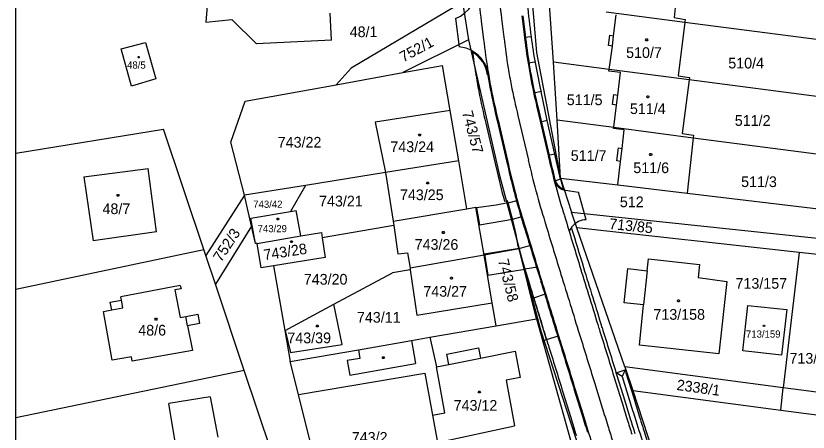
# Model space of a CAD drawing. Extents: x -639590 to -639298, y -1193269 to -1192863.
# Drawn here: x -639590.4 to -639464.3, y -1193049.8 to -1192983.6 of the extents above; entities that cross this region are included whole.
import ezdxf

# ---------------------------------------------------------------- set-up
doc = ezdxf.new("R2010")
doc.units = 0
for name, color, linetype in [('Vrstva 1', 7, 'Continuous'), ('Vrstva 19', 7, 'Continuous'), ('Vrstva 2', 7, 'Continuous'), ('Vrstva 20', 7, 'Continuous'), ('Vrstva 21', 7, 'Continuous'), ('Vrstva 4', 7, 'Continuous'), ('Vrstva 5', 7, 'Continuous'), ('Vrstva 61', 7, 'Continuous')]:
    doc.layers.add(name, color=color, linetype=linetype)

msp = doc.modelspace()

# ---------------------------------------------------------------- linework, layer by layer
at = {"layer": 'Vrstva 1'}
for p, q in [((-639558.69, -1192965.64), (-639560.13, -1192984.63)), ((-639509.02, -1192971.25), (-639507.5, -1192989.45)), ((-639484.75, -1192975.37), (-639485.61, -1192983.86)), ((-639519.26, -1192981.41), (-639537.01, -1192991.95)), ((-639519.26, -1192981.41), (-639518.33, -1192987.4)), ((-639504.82, -1192990.96), (-639505.43, -1192981.79)), ((-639540.12, -1192987.45), (-639540.36, -1192983.16)), ((-639496.42, -1192982.96), (-639483.9, -1192984.59)), ((-639485.61, -1192983.86), (-639483.85, -1192984.2)), ((-639560.13, -1192984.63), (-639555.99, -1192984.2)), ((-639555.99, -1192984.2), (-639552.08, -1192988.04)), ((-639483.9, -1192984.59), (-639484.96, -1192993.13)), ((-639483.85, -1192984.2), (-639483.9, -1192984.59)), ((-639483.9, -1192984.59), (-639461.13, -1192987.55)), ((-639540.12, -1192987.45), (-639552.08, -1192988.04)), ((-639518.33, -1192987.4), (-639528.76, -1192992.62)), ((-639518.33, -1192987.4), (-639513.38, -1193008.98)), ((-639573.61, -1192988.84), (-639569.73, -1192987.84)), ((-639571.96, -1192994.78), (-639573.61, -1192988.84)), ((-639569.73, -1192987.84), (-639568.13, -1192993.61)), ((-639507.5, -1192989.45), (-639503.7, -1193009.43)), ((-639504.21, -1193000.14), (-639504.82, -1192990.96)), ((-639495.93, -1192992.12), (-639504.82, -1192990.96)), ((-639537.01, -1192991.95), (-639539.42, -1192994.56)), ((-639539.42, -1192994.56), (-639528.76, -1192992.62)), ((-639528.76, -1192992.62), (-639522.49, -1192991.48)), ((-639521.26, -1192998.64), (-639522.49, -1192991.48)), ((-639495.97, -1192992.38), (-639495.93, -1192992.12)), ((-639494.14, -1192992.64), (-639495.97, -1192992.38)), ((-639483.21, -1192993.78), (-639495.93, -1192992.12)), ((-639494.57, -1192996.2), (-639494.14, -1192992.64)), ((-639568.13, -1192993.61), (-639571.96, -1192994.78)), ((-639484.96, -1192993.13), (-639483.16, -1192993.4)), ((-639483.21, -1192993.78), (-639484.31, -1193002.34)), ((-639483.16, -1192993.4), (-639483.21, -1192993.78)), ((-639460.55, -1192996.75), (-639483.21, -1192993.78)), ((-639553.86, -1192997.18), (-639539.42, -1192994.56)), ((-639495.4, -1192997.71), (-639495.21, -1192996.13)), ((-639495.21, -1192996.13), (-639494.57, -1192996.2)), ((-639556.15, -1193003.67), (-639553.86, -1192997.18)), ((-639494.77, -1192997.79), (-639495.4, -1192997.71)), ((-639521.26, -1192998.64), (-639533.19, -1193000.49)), ((-639519.89, -1193006.67), (-639521.26, -1192998.64)), ((-639495.21, -1193001.32), (-639494.77, -1192997.79)), ((-639503.7, -1193009.43), (-639504.21, -1193000.14)), ((-639504.21, -1193000.14), (-639495.21, -1193001.32)), ((-639533.19, -1193000.49), (-639531.56, -1193008.54)), ((-639495.23, -1193001.51), (-639495.21, -1193001.32)), ((-639493.52, -1193001.76), (-639495.23, -1193001.51)), ((-639495.21, -1193001.32), (-639482.56, -1193002.99)), ((-639590.39, -1193005.46), (-639566.86, -1193001.65)), ((-639560.45, -1193020.79), (-639566.86, -1193001.65)), ((-639493.88, -1193004.68), (-639493.52, -1193001.76)), ((-639484.31, -1193002.34), (-639482.51, -1193002.57)), ((-639482.51, -1193002.57), (-639482.56, -1193002.99)), ((-639553.99, -1193012.12), (-639556.15, -1193003.67)), ((-639482.56, -1193002.99), (-639483.54, -1193011.82)), ((-639482.56, -1193002.99), (-639459.99, -1193005.96)), ((-639494.73, -1193006.69), (-639494.47, -1193004.61)), ((-639494.47, -1193004.61), (-639493.88, -1193004.68)), ((-639519.89, -1193006.67), (-639531.56, -1193008.54)), ((-639518.6, -1193014.29), (-639519.89, -1193006.67)), ((-639494.13, -1193006.76), (-639494.73, -1193006.69)), ((-639494.58, -1193010.51), (-639494.13, -1193006.76)), ((-639579.55, -1193009.22), (-639569.3, -1193007.9)), ((-639568, -1193017.94), (-639569.3, -1193007.9)), ((-639531.56, -1193008.54), (-639544.27, -1193010.57)), ((-639531.56, -1193008.54), (-639530.31, -1193016.28)), ((-639513.38, -1193008.98), (-639510.28, -1193020.67)), ((-639579.55, -1193009.22), (-639578.08, -1193019.37)), ((-639503.7, -1193009.43), (-639501.94, -1193014.81)), ((-639503.7, -1193009.43), (-639494.58, -1193010.51)), ((-639544.27, -1193010.57), (-639553.99, -1193012.12)), ((-639544.27, -1193010.57), (-639546.64, -1193014.7)), ((-639494.58, -1193010.51), (-639483.54, -1193011.82)), ((-639553.99, -1193012.12), (-639560.14, -1193021.73)), ((-639552.87, -1193017.05), (-639553.99, -1193012.12)), ((-639483.54, -1193011.82), (-639459.46, -1193014.67)), ((-639518.6, -1193014.29), (-639517.16, -1193014.04)), ((-639515.83, -1193021.66), (-639517.16, -1193014.04)), ((-639552.97, -1193015.81), (-639546.64, -1193014.7)), ((-639546.64, -1193014.7), (-639545.76, -1193014.55)), ((-639545.02, -1193018.62), (-639545.76, -1193014.55)), ((-639530.31, -1193016.28), (-639518.6, -1193014.29)), ((-639501.94, -1193014.81), (-639408.9, -1193024.71)), ((-639501.06, -1193017.35), (-639501.94, -1193014.81)), ((-639552.24, -1193019.83), (-639552.97, -1193015.81)), ((-639530.31, -1193016.28), (-639530.22, -1193016.93)), ((-639568, -1193017.94), (-639578.08, -1193019.37)), ((-639552.87, -1193017.05), (-639558.61, -1193026.29)), ((-639552.24, -1193019.83), (-639552.87, -1193017.05)), ((-639530.22, -1193016.93), (-639541.62, -1193018.94)), ((-639530.22, -1193016.93), (-639529.57, -1193021.47)), ((-639493.42, -1193039.43), (-639501.06, -1193017.35)), ((-639465.69, -1193021.25), (-639501.06, -1193017.35)), ((-639551.96, -1193019.82), (-639545.02, -1193018.62)), ((-639545.02, -1193018.62), (-639541.75, -1193018.05)), ((-639541.75, -1193018.05), (-639541.62, -1193018.94)), ((-639541.62, -1193018.94), (-639541.16, -1193022.03)), ((-639551.96, -1193019.82), (-639552.24, -1193019.83)), ((-639551.34, -1193023.7), (-639551.96, -1193019.82)), ((-639590.39, -1193027.1), (-639560.45, -1193020.79)), ((-639560.14, -1193021.73), (-639560.45, -1193020.79)), ((-639529.57, -1193021.47), (-639528.05, -1193021.28)), ((-639528.05, -1193021.28), (-639527.62, -1193023.76)), ((-639515.83, -1193021.66), (-639527.62, -1193023.76)), ((-639510.28, -1193020.67), (-639515.83, -1193021.66)), ((-639514.54, -1193029.25), (-639515.83, -1193021.66)), ((-639507.5, -1193031.78), (-639510.28, -1193020.67)), ((-639510.28, -1193020.67), (-639506.87, -1193033.57)), ((-639465.69, -1193021.25), (-639468.21, -1193042.77)), ((-639440.59, -1193024.01), (-639465.69, -1193021.25)), ((-639558.61, -1193026.29), (-639560.14, -1193021.73)), ((-639541.16, -1193022.03), (-639549.38, -1193023.38)), ((-639489.86, -1193024.14), (-639489.66, -1193022.27)), ((-639489.66, -1193022.27), (-639481.57, -1193023.17)), ((-639549.38, -1193023.38), (-639551.34, -1193023.7)), ((-639549.38, -1193023.38), (-639547.58, -1193033.68)), ((-639527.59, -1193024.01), (-639530.44, -1193024.49)), ((-639527.62, -1193023.76), (-639527.59, -1193024.01)), ((-639527.59, -1193024.01), (-639526.56, -1193031.23)), ((-639493.53, -1193029.25), (-639492.95, -1193023.81)), ((-639492.95, -1193023.81), (-639489.86, -1193024.14)), ((-639481.57, -1193023.17), (-639481.74, -1193025.25)), ((-639539.76, -1193029.49), (-639530.44, -1193024.49)), ((-639481.74, -1193025.25), (-639477.2, -1193025.86)), ((-639564.24, -1193026.51), (-639573.66, -1193028.32)), ((-639564.24, -1193026.51), (-639564.09, -1193027.02)), ((-639554.02, -1193040.01), (-639558.61, -1193026.29)), ((-639477.2, -1193025.86), (-639478.47, -1193037.37)), ((-639564.09, -1193027.02), (-639565.06, -1193027.2)), ((-639565.06, -1193027.2), (-639564.21, -1193031.61)), ((-639575.35, -1193029.14), (-639573.57, -1193028.81)), ((-639575.13, -1193030.37), (-639575.35, -1193029.14)), ((-639573.57, -1193028.81), (-639573.66, -1193028.32)), ((-639526.56, -1193031.23), (-639514.54, -1193029.25)), ((-639513.92, -1193032.9), (-639514.54, -1193029.25)), ((-639490.45, -1193029.58), (-639493.53, -1193029.25)), ((-639576.45, -1193030.61), (-639575.13, -1193030.37)), ((-639547.5, -1193033.64), (-639539.76, -1193029.49)), ((-639538.45, -1193035.9), (-639539.76, -1193029.49)), ((-639491.13, -1193035.97), (-639490.45, -1193029.58)), ((-639474.65, -1193036.9), (-639473.85, -1193029.69)), ((-639473.85, -1193029.69), (-639467.63, -1193030.32)), ((-639467.63, -1193030.32), (-639468.48, -1193037.59)), ((-639575.05, -1193038.4), (-639576.45, -1193030.61)), ((-639564.21, -1193031.61), (-639563.32, -1193031.44)), ((-639563.32, -1193031.44), (-639561.44, -1193031.08)), ((-639561.44, -1193031.08), (-639561.16, -1193032.56)), ((-639513.92, -1193032.9), (-639507.5, -1193031.78)), ((-639507.5, -1193031.78), (-639502.09, -1193051.09)), ((-639561.16, -1193032.56), (-639563.04, -1193032.92)), ((-639563.04, -1193032.92), (-639562.28, -1193036.82)), ((-639524.47, -1193034.73), (-639513.92, -1193032.9)), ((-639547.58, -1193033.68), (-639547.5, -1193033.64)), ((-639547.58, -1193033.68), (-639546.72, -1193038.6)), ((-639547.5, -1193033.64), (-639546.65, -1193037.16)), ((-639506.87, -1193033.57), (-639486.01, -1193097.33)), ((-639535.86, -1193036.71), (-639527.4, -1193035.24)), ((-639527.4, -1193035.24), (-639524.47, -1193034.73)), ((-639524.47, -1193034.73), (-639523.42, -1193039.45)), ((-639562.28, -1193036.82), (-639571.85, -1193038.54)), ((-639546.72, -1193038.6), (-639535.86, -1193036.71)), ((-639546.65, -1193037.16), (-639538.45, -1193035.9)), ((-639521.77, -1193037.44), (-639516.75, -1193036.43)), ((-639516.75, -1193036.43), (-639516.42, -1193038.04)), ((-639478.47, -1193037.37), (-639491.13, -1193035.97)), ((-639571.98, -1193037.85), (-639575.05, -1193038.4)), ((-639571.85, -1193038.54), (-639571.98, -1193037.85)), ((-639521.44, -1193039.05), (-639521.77, -1193037.44)), ((-639516.42, -1193038.04), (-639510.92, -1193036.93)), ((-639510.92, -1193036.93), (-639510.1, -1193041.14)), ((-639468.48, -1193037.59), (-639474.65, -1193036.9)), ((-639545.4, -1193043.83), (-639546.72, -1193038.6)), ((-639523.42, -1193039.45), (-639521.44, -1193039.05)), ((-639554.02, -1193040.01), (-639590.39, -1193047.55)), ((-639547.47, -1193059.58), (-639554.02, -1193040.01)), ((-639545.4, -1193043.83), (-639525.28, -1193040.46)), ((-639525.28, -1193040.46), (-639524.07, -1193047.11)), ((-639468.21, -1193042.77), (-639493.42, -1193039.43)), ((-639493.42, -1193039.43), (-639492.18, -1193043.2)), ((-639510.1, -1193041.14), (-639512.32, -1193041.56)), ((-639512.32, -1193041.56), (-639511.02, -1193048.83)), ((-639468.63, -1193046.32), (-639468.21, -1193042.77)), ((-639443.02, -1193046.1), (-639468.21, -1193042.77)), ((-639559.45, -1193044.19), (-639566.02, -1193045.25)), ((-639559.45, -1193044.19), (-639558.24, -1193050.62)), ((-639541.72, -1193058.45), (-639545.4, -1193043.83)), ((-639492.18, -1193043.2), (-639468.63, -1193046.32)), ((-639492.18, -1193043.2), (-639479.86, -1193080.55)), ((-639564.97, -1193051.71), (-639566.02, -1193045.25)), ((-639468.63, -1193046.32), (-639443.41, -1193049.65)), ((-639524.07, -1193047.11), (-639523.28, -1193051.49)), ((-639523.28, -1193051.49), (-639511.02, -1193048.83))]:
    msp.add_line(p, q, dxfattribs=at)
at = {"layer": 'Vrstva 19'}
for p, q in [((-639509.85, -1192983.61), (-639509.47, -1192986.58)), ((-639516.29, -1192984.43), (-639515.92, -1192987.39)), ((-639507.29, -1192998.74), (-639505.63, -1193005.84)), ((-639513.62, -1193000.21), (-639511.97, -1193007.31)), ((-639503.06, -1193015.39), (-639502.84, -1193016.13)), ((-639509.28, -1193017.3), (-639509.05, -1193018.03)), ((-639495.19, -1193040.97), (-639493.94, -1193044.98)), ((-639494.71, -1193040.82), (-639493.46, -1193044.84)), ((-639501.39, -1193042.89), (-639500.15, -1193046.91))]:
    msp.add_line(p, q, dxfattribs=at)
for points in [[(-639513.07, -1192984.02), (-639512.69, -1192986.99)], [(-639510.45, -1192999.47), (-639508.8, -1193006.58)], [(-639506.17, -1193016.34), (-639505.94, -1193017.08)], [(-639498.29, -1193041.92), (-639497.04, -1193045.95)]]:
    msp.add_lwpolyline(points, dxfattribs=at)
for centre, radius, start, end in [((-639366.33, -1192964.54), 151.28, 185.6271, 187.5624), ((-639366.33, -1192964.54), 148.03, 185.6271, 187.5624), ((-639365.74, -1192969.2), 151.28, 186.9003, 188.8357), ((-639365.74, -1192969.2), 148.03, 186.9003, 188.8357), ((-639365.74, -1192969.2), 144.78, 186.9003, 188.8357), ((-639437.96, -1192980.02), 71.75, 189.1405, 191.2012), ((-639437.96, -1192980.02), 78.25, 189.1405, 191.2012), ((-639437.96, -1192980.02), 75, 189.1405, 191.2012), ((-639362.58, -1192964.2), 148.78, 191.5316, 193.416), ((-639362.58, -1192964.2), 152.03, 191.5316, 193.416), ((-639362.58, -1192964.2), 155.28, 191.5316, 193.416), ((-639364.44, -1192973.83), 148.03, 192.7793, 194.7147), ((-639364.44, -1192973.83), 144.78, 192.7793, 194.7147), ((-639364.44, -1192973.83), 151.28, 192.7793, 194.7147), ((-639435.18, -1192992), 75, 195.0195, 195.1112), ((-639356.99, -1192969.88), 156.25, 195.467, 197.3005), ((-639435.18, -1192992), 71.75, 195.0195, 195.1112), ((-639356.99, -1192969.88), 153, 195.467, 197.3005), ((-639435.18, -1192992), 78.25, 195.0195, 195.1112), ((-639356.99, -1192969.88), 159.5, 195.467, 197.3005), ((-630394.5, -1190229.42), 9525.1, 197.011551, 197.059693), ((-630399.5, -1190230.95), 9523.13, 197.011568, 197.0597), ((-630394.5, -1190229.42), 9524.6, 197.019792, 197.059693), ((-630394.5, -1190229.42), 9531.6, 197.011551, 197.059693), ((-634723.8, -1191557.36), 4996.72, 197.06619, 197.18066), ((-634723.8, -1191557.36), 4996.22, 197.06619, 197.18066), ((-634723.8, -1191557.36), 4999.97, 197.06619, 197.18066), ((-634723.8, -1191557.36), 5003.22, 197.06619, 197.18066), ((-629444.52, -1189923.42), 10526.31, 197.189448, 197.232992), ((-629444.52, -1189923.42), 10523.06, 197.189448, 197.232992), ((-629444.52, -1189923.42), 10522.56, 197.189448, 197.232992), ((-629444.52, -1189923.42), 10529.56, 197.189448, 197.232992), ((-638520.02, -1192743.51), 1019.51, 197.19976, 197.36783), ((-638520.02, -1192743.51), 1019.01, 197.19976, 197.36783), ((-638520.02, -1192743.51), 1026.01, 197.19976, 197.36783), ((-638520.02, -1192743.51), 1022.76, 197.19976, 197.36783), ((-639019.03, -1192899.3), 496.75, 197.3984, 197.6812), ((-639019.03, -1192899.3), 496.25, 197.3984, 197.6812), ((-639019.03, -1192899.3), 500, 197.3984, 197.6812), ((-639019.03, -1192899.3), 503.25, 197.3984, 197.6812)]:
    msp.add_arc(centre, radius, start, end, dxfattribs=at)
at = {"layer": 'Vrstva 20'}
for p, q in [((-639509.7, -1192983.59), (-639509.32, -1192986.56)), ((-639508.35, -1192986.93), (-639509.41, -1192987.06)), ((-639507.75, -1192990.95), (-639508.85, -1192991.11)), ((-639515.15, -1192992.85), (-639515.3, -1192992.87)), ((-639506.78, -1192995.64), (-639507.94, -1192995.9)), ((-639507.14, -1192998.7), (-639505.49, -1193005.8)), ((-639513.76, -1193000.25), (-639512.11, -1193007.35)), ((-639505.78, -1193000.25), (-639506.88, -1193000.51)), ((-639515.57, -1193000.67), (-639513.91, -1193007.77)), ((-639504.59, -1193005.6), (-639505.63, -1193005.84)), ((-639503.66, -1193009.57), (-639504.66, -1193009.88)), ((-639503.66, -1193009.57), (-639503.22, -1193011.26)), ((-639512.02, -1193013.34), (-639510.56, -1193012.95)), ((-639511.32, -1193015.96), (-639509.81, -1193015.54)), ((-639509.42, -1193017.34), (-639509.2, -1193018.07)), ((-639510.27, -1193020.63), (-639508.43, -1193020.08)), ((-639507.36, -1193023.57), (-639509.35, -1193023.89)), ((-639507.95, -1193028.44), (-639506.05, -1193027.81)), ((-639505.9, -1193035.1), (-639503.99, -1193034.52)), ((-639501.54, -1193042.94), (-639500.29, -1193046.95)), ((-639503.3, -1193043.48), (-639502.06, -1193047.5))]:
    msp.add_line(p, q, dxfattribs=at)
for points in [[(-639503.66, -1193009.57), (-639504.59, -1193005.6), (-639505.78, -1193000.25), (-639506.78, -1192995.64)], [(-639509.89, -1193022.13), (-639509.89, -1193022.13), (-639510.27, -1193020.63), (-639510.43, -1193020.22), (-639510.76, -1193018.38), (-639511.29, -1193016.1), (-639512.1, -1193013.05), (-639512.59, -1193013.14)]]:
    msp.add_lwpolyline(points, dxfattribs=at)
for points in [[(-639516.57, -1193016.83), (-639511.32, -1193015.96), (-639512.02, -1193013.34), (-639513.93, -1193013.71), (-639517.05, -1193014.15)], [(-639510.27, -1193020.63), (-639515.77, -1193021.53), (-639515.24, -1193024.83), (-639509.35, -1193023.89), (-639509.86, -1193022.27)], [(-639506.38, -1193035.25), (-639505.9, -1193035.1), (-639507.95, -1193028.44), (-639508.25, -1193028.54), (-639507.45, -1193031.45)]]:
    msp.add_lwpolyline(points, close=True, dxfattribs=at)
for centre, radius, start, end in [((-639417.6, -1192974.02), 91.67, 184.8348, 188.0943), ((-639365.74, -1192969.2), 144.63, 186.9003, 188.8357), ((-639426.32, -1192976.59), 82.68, 187.1865, 193.326), ((-639365.74, -1192969.2), 153.28, 187.5007, 188.8357), ((-639520.24, -1192993.7), 5.01, 8.1002, 59.2759), ((-639437.96, -1192980.02), 71.6, 189.1405, 191.2012), ((-639437.96, -1192980.02), 80.25, 189.1405, 191.2012), ((-639437.96, -1192980.02), 78.4, 189.3512, 191.2012), ((-639362.58, -1192964.2), 148.63, 191.5316, 193.416), ((-639362.58, -1192964.2), 157.28, 191.5316, 193.416), ((-639362.58, -1192964.2), 155.43, 191.5316, 193.416), ((-639364.44, -1192973.83), 144.63, 192.7793, 194.346), ((-639364.44, -1192973.83), 153.28, 192.7793, 194.8609), ((-639364.44, -1192973.83), 151.43, 192.7793, 194.7147), ((-639502.55, -1193009.14), 2.08, 194.5353, 249.6911), ((-639435.18, -1192992), 78.4, 195.0195, 195.1112), ((-639356.99, -1192969.88), 159.65, 195.467, 197.3005), ((-630394.5, -1190229.42), 9531.75, 197.011551, 197.059693), ((-630394.5, -1190229.42), 9533.6, 197.033673, 197.059693), ((-634723.8, -1191557.36), 5005.22, 197.06619, 197.18066), ((-634723.8, -1191557.36), 5003.37, 197.06619, 197.18066), ((-629444.52, -1189923.42), 10529.71, 197.189448, 197.232992), ((-629444.52, -1189923.42), 10531.56, 197.189448, 197.232992), ((-638520.02, -1192743.51), 1026.16, 197.19976, 197.36783), ((-638520.02, -1192743.51), 1028.01, 197.19976, 197.36783)]:
    msp.add_arc(centre, radius, start, end, dxfattribs=at)
at = {"layer": 'Vrstva 21'}
for p, q in [((-639520.38, -1192984.02), (-639519.8, -1192988.56)), ((-639502.91, -1193011.34), (-639500.84, -1193011.64)), ((-639502.49, -1193011.4), (-639502.27, -1193011.43)), ((-639499.62, -1193016.03), (-639500.84, -1193011.64)), ((-639494.84, -1193040.39), (-639493.41, -1193039.94)), ((-639493.88, -1193040.95), (-639494.84, -1193040.39)), ((-639493.41, -1193039.94), (-639493.88, -1193040.95)), ((-639493.28, -1193040.37), (-639492.03, -1193044.39)), ((-639490.41, -1193049.57), (-639489.49, -1193052.41))]:
    msp.add_line(p, q, dxfattribs=at)
msp.add_lwpolyline([(-639493.88, -1193040.95), (-639492.75, -1193044.61)], dxfattribs=at)
for centre, radius, start, end in [((-639522.44, -1192978.92), 5.5, 291.9686, 3.3126), ((-639520.04, -1192993.05), 4.5, 58.7232, 86.9787), ((-639520.24, -1192993.7), 5.16, 8.1002, 60.5785), ((-639502.55, -1193009.14), 2.23, 198.1964, 260.6084), ((-639499.51, -1193019.03), 3, 115.822, 158.0478), ((-639499.51, -1193019.03), 3, 92.0809, 115.8297), ((-668645.41, -1202074.69), 30519.93, 17.218354, 17.219185), ((-638520.02, -1192743.51), 1017.51, 197.19976, 197.36783), ((-638519.74, -1192743.42), 1018.56, 197.1997, 197.36766), ((-639019.03, -1192899.3), 495.5, 197.3984, 197.9106), ((-639019.03, -1192899.3), 494.75, 197.3984, 197.6812)]:
    msp.add_arc(centre, radius, start, end, dxfattribs=at)
at = {"layer": 'Vrstva 4'}
for p, q in [((-639495.22, -1192986.76), (-639494.82, -1192983.46)), ((-639496.02, -1192988.32), (-639495.82, -1192986.69)), ((-639495.82, -1192986.69), (-639495.22, -1192986.76)), ((-639495.42, -1192988.4), (-639495.22, -1192986.76)), ((-639495.42, -1192988.4), (-639496.02, -1192988.32)), ((-639495.93, -1192992.12), (-639495.42, -1192988.4)), ((-639494.77, -1192997.79), (-639494.57, -1192996.2)), ((-639494.13, -1193006.76), (-639493.88, -1193004.68)), ((-639489.86, -1193024.14), (-639490.45, -1193029.58)), ((-639573.35, -1193030.05), (-639573.57, -1193028.81)), ((-639575.13, -1193030.37), (-639573.35, -1193030.05)), ((-639563.04, -1193032.92), (-639563.32, -1193031.44)), ((-639527.4, -1193035.24), (-639526.76, -1193038.93)), ((-639535.86, -1193036.71), (-639535.62, -1193038.09)), ((-639535.62, -1193038.09), (-639537.62, -1193038.44)), ((-639521.44, -1193039.05), (-639516.42, -1193038.04)), ((-639537.62, -1193038.44), (-639537.22, -1193040.75)), ((-639537.22, -1193040.75), (-639526.76, -1193038.93)), ((-639522.1, -1193046.75), (-639523.42, -1193039.45)), ((-639524.07, -1193047.11), (-639522.1, -1193046.75))]:
    msp.add_line(p, q, dxfattribs=at)
at = {"layer": 'Vrstva 5'}
for points in [[(-639489.89, -1192987.26), (-639489.8, -1192987.41), (-639489.89, -1192987.56), (-639490.07, -1192987.56), (-639490.16, -1192987.41), (-639490.07, -1192987.26)], [(-639570.77, -1192990.08), (-639570.71, -1192990.18), (-639570.77, -1192990.28), (-639570.89, -1192990.28), (-639570.95, -1192990.18), (-639570.89, -1192990.08)], [(-639489.69, -1192996.32), (-639489.6, -1192996.47), (-639489.69, -1192996.62), (-639489.87, -1192996.62), (-639489.96, -1192996.47), (-639489.87, -1192996.32)], [(-639526, -1193002.41), (-639525.91, -1193002.56), (-639526, -1193002.71), (-639526.18, -1193002.71), (-639526.27, -1193002.56), (-639526.18, -1193002.41)], [(-639489.22, -1193005.52), (-639489.13, -1193005.67), (-639489.22, -1193005.82), (-639489.4, -1193005.82), (-639489.49, -1193005.67), (-639489.4, -1193005.52)], [(-639524.73, -1193010.04), (-639524.64, -1193010.19), (-639524.73, -1193010.34), (-639524.91, -1193010.34), (-639525, -1193010.19), (-639524.91, -1193010.04)], [(-639574.03, -1193012.01), (-639573.94, -1193012.16), (-639574.03, -1193012.31), (-639574.21, -1193012.31), (-639574.3, -1193012.16), (-639574.21, -1193012.01)], [(-639548.59, -1193015.77), (-639548.5, -1193015.92), (-639548.59, -1193016.07), (-639548.77, -1193016.07), (-639548.86, -1193015.92), (-639548.77, -1193015.77)], [(-639522.25, -1193017.92), (-639522.16, -1193018.07), (-639522.25, -1193018.22), (-639522.43, -1193018.22), (-639522.52, -1193018.07), (-639522.43, -1193017.92)], [(-639546.42, -1193019.38), (-639546.33, -1193019.53), (-639546.42, -1193019.68), (-639546.6, -1193019.68), (-639546.69, -1193019.53), (-639546.6, -1193019.38)], [(-639520.94, -1193025.17), (-639520.85, -1193025.32), (-639520.94, -1193025.47), (-639521.12, -1193025.47), (-639521.21, -1193025.32), (-639521.12, -1193025.17)], [(-639484.81, -1193028.78), (-639484.72, -1193028.93), (-639484.81, -1193029.08), (-639484.99, -1193029.08), (-639485.08, -1193028.93), (-639484.99, -1193028.78)], [(-639568, -1193031.7), (-639567.91, -1193031.85), (-639568, -1193032), (-639568.18, -1193032), (-639568.27, -1193031.85), (-639568.18, -1193031.7)], [(-639542.29, -1193032.79), (-639542.2, -1193032.94), (-639542.29, -1193033.09), (-639542.47, -1193033.09), (-639542.56, -1193032.94), (-639542.47, -1193032.79)], [(-639471.22, -1193032.83), (-639471.16, -1193032.93), (-639471.22, -1193033.03), (-639471.34, -1193033.03), (-639471.4, -1193032.93), (-639471.34, -1193032.83)], [(-639531.8, -1193037.83), (-639531.71, -1193037.98), (-639531.8, -1193038.13), (-639531.98, -1193038.13), (-639532.07, -1193037.98), (-639531.98, -1193037.83)], [(-639516.51, -1193043.29), (-639516.42, -1193043.44), (-639516.51, -1193043.59), (-639516.69, -1193043.59), (-639516.78, -1193043.44), (-639516.69, -1193043.29)]]:
    msp.add_lwpolyline(points, close=True, dxfattribs=at)
at = {"layer": 'Vrstva 61'}
msp.add_lwpolyline([(-639590.39, -1193268.77), (-639590.39, -1192863.27)], dxfattribs=at)

# ---------------------------------------------------------------- texts
at = {"layer": 'Vrstva 2'}
for s, height, p in [('48/1', 1.7, (-639537.24, -1192986.99)), ('510/7', 1.7, (-639493.24, -1192990.3)), ('510/4', 1.7, (-639476.97, -1192991.97)), ('48/5', 1.14, (-639572.68, -1192992)), ('511/5', 1.7, (-639502.68, -1192997.81)), ('511/4', 1.7, (-639492.63, -1192999.22)), ('511/2', 1.7, (-639475.93, -1193001.1)), ('743/22', 1.7, (-639548.7, -1193004.56)), ('743/24', 1.7, (-639530.77, -1193005.28)), ('511/7', 1.7, (-639502.05, -1193006.68)), ('511/6', 1.7, (-639492.09, -1193008.62)), ('511/3', 1.7, (-639474.93, -1193010.84)), ('743/25', 1.7, (-639529.24, -1193012.92)), ('743/21', 1.7, (-639542.12, -1193013.92)), ('512', 1.7, (-639494.23, -1193014.04)), ('48/7', 1.7, (-639576.59, -1193015.14)), ('743/42', 1.14, (-639552.6, -1193014.14)), ('743/29', 1.14, (-639551.9, -1193018.02)), ('743/26', 1.7, (-639526.9, -1193020.82)), ('743/20', 1.7, (-639544.55, -1193026.36)), ('713/157', 1.7, (-639475.82, -1193027.01)), ('743/27', 1.7, (-639525.52, -1193028.28)), ('713/158', 1.7, (-639488.89, -1193031.95)), ('743/11', 1.7, (-639536.09, -1193032.41)), ('48/6', 1.7, (-639570.9, -1193034.46)), ('743/39', 1.7, (-639547.17, -1193035.68)), ('713/159', 1.14, (-639474.16, -1193034.79)), ('713/2', 1.7, (-639467.23, -1193038.93)), ('743/12', 1.7, (-639520.69, -1193046.42)), ('743/2', 1.7, (-639536.91, -1193051.51))]:
    msp.add_text(s, height=height, dxfattribs=at).set_placement(p)
for s, rotation, p in [('752/1', 28.2468, (-639528.71, -1192991.02)), ('743/57', 284.9892, (-639519.37, -1192998.95)), ('713/85', 354.0879, (-639495.99, -1193017.49)), ('752/3', 56.6082, (-639557.7, -1193022.89)), ('743/28', 8.7663, (-639550.82, -1193022.49)), ('743/58', 283.8433, (-639513.65, -1193022.5)), ('2338/1', 352.1399, (-639485.27, -1193043.11))]:
    msp.add_text(s, height=1.7, rotation=rotation, dxfattribs=at).set_placement(p)

doc.saveas('drawing.dxf')
